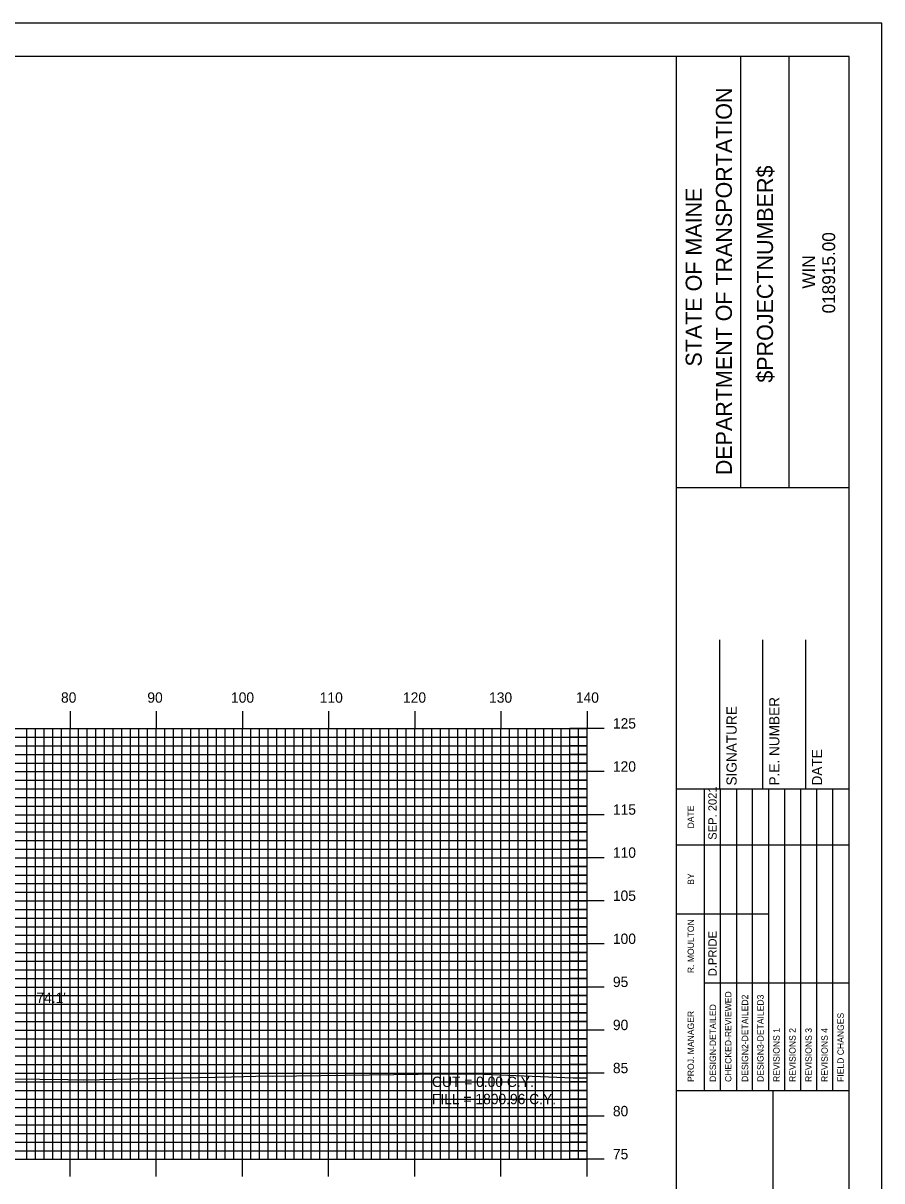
# Model space of a CAD drawing. Extents: x -302 to 42, y -1658 to -1438.
# Drawn here: x -61.3 to 38.3, y -1572.1 to -1437.7 of the extents above; entities that cross this region are included whole.
import ezdxf

# ---------------------------------------------------------------- set-up
doc = ezdxf.new("R2010")
doc.units = 0
for name, color, linetype in [('BORDER', 7, 'Continuous'), ('D_Text_Standard', 7, 'Continuous'), ('H_V ANNOTATION', 7, 'Continuous'), ('MAJOR', 7, 'Continuous'), ('MINOR', 7, 'Continuous'), ('PLOT BOUNDARY', 7, 'Continuous'), ('S_Roadway_Centerline', 7, 'Continuous')]:
    doc.layers.add(name, color=color, linetype=linetype)

msp = doc.modelspace()

# ---------------------------------------------------------------- linework, layer by layer
at = {"layer": 'BORDER'}
for p, q in [((14.51, -1651.6), (14.51, -1441.6)), ((21.97, -1491.61), (21.97, -1441.61)), ((27.56, -1491.61), (27.56, -1441.61)), ((14.51, -1491.62), (34.51, -1491.62)), ((19.51, -1526.6), (19.51, -1509.3)), ((24.51, -1526.6), (24.51, -1509.3)), ((29.51, -1526.6), (29.51, -1509.3)), ((14.51, -1526.6), (34.51, -1526.6)), ((14.51, -1561.6), (34.51, -1561.6)), ((25.69, -1631.6), (25.69, -1561.6))]:
    msp.add_line(p, q, dxfattribs=at)
msp.add_lwpolyline([(-285.49, -1651.6), (34.51, -1651.6), (34.51, -1441.6), (-285.49, -1441.6)], close=True, dxfattribs=at)
for points in [[(17.74, -1533.1), (17.74, -1526.6)], [(19.6, -1561.59), (19.6, -1526.6)], [(21.47, -1526.6), (21.47, -1561.59)], [(23.33, -1561.59), (23.33, -1526.6)], [(25.19, -1561.59), (25.19, -1526.6)], [(27.06, -1561.59), (27.06, -1526.6)], [(28.92, -1561.59), (28.92, -1526.6)], [(30.78, -1561.59), (30.78, -1526.6)], [(32.65, -1561.59), (32.65, -1526.6)], [(17.74, -1561.59), (17.74, -1528.01)], [(14.51, -1533.1), (34.51, -1533.1)], [(14.51, -1541.1), (17.74, -1541.1)], [(17.74, -1541.1), (25.19, -1541.1)], [(17.74, -1549.1), (34.51, -1549.1)]]:
    msp.add_lwpolyline(points, dxfattribs=at)
at = {"layer": 'MAJOR'}
for p, q in [((-55.89, -1517.6), (-55.89, -1519.6)), ((-45.89, -1517.6), (-45.89, -1519.6)), ((-35.89, -1517.6), (-35.89, -1519.6)), ((-25.89, -1517.6), (-25.89, -1519.6)), ((-15.89, -1517.6), (-15.89, -1519.6)), ((-5.89, -1517.6), (-5.89, -1519.6)), ((4.11, -1517.6), (4.11, -1519.6)), ((-275.89, -1519.6), (4.11, -1519.6)), ((-275.89, -1519.6), (4.11, -1519.6)), ((-55.89, -1569.6), (-55.89, -1519.6)), ((-45.89, -1569.6), (-45.89, -1519.6)), ((-35.89, -1569.6), (-35.89, -1519.6)), ((-25.89, -1569.6), (-25.89, -1519.6)), ((-15.89, -1569.6), (-15.89, -1519.6)), ((-5.89, -1569.6), (-5.89, -1519.6)), ((6.11, -1519.6), (2.1, -1519.6)), ((4.11, -1569.6), (4.11, -1519.6)), ((4.11, -1569.6), (4.11, -1519.6)), ((-275.89, -1524.6), (4.11, -1524.6)), ((6.11, -1524.6), (2.1, -1524.6)), ((-275.89, -1529.6), (4.11, -1529.6)), ((6.11, -1529.6), (2.1, -1529.6)), ((-275.89, -1534.6), (4.11, -1534.6)), ((6.11, -1534.6), (2.1, -1534.6)), ((-275.89, -1539.6), (4.11, -1539.6)), ((6.11, -1539.6), (2.1, -1539.6)), ((-275.89, -1544.6), (4.11, -1544.6)), ((6.11, -1544.6), (2.1, -1544.6)), ((-275.89, -1549.6), (4.11, -1549.6)), ((6.11, -1549.6), (2.1, -1549.6)), ((-275.89, -1554.6), (4.11, -1554.6)), ((6.11, -1554.6), (2.1, -1554.6)), ((-275.89, -1559.6), (4.11, -1559.6)), ((6.11, -1559.6), (2.1, -1559.6)), ((-275.89, -1564.6), (4.11, -1564.6)), ((6.11, -1564.6), (2.1, -1564.6)), ((-275.89, -1569.6), (4.11, -1569.6)), ((-275.89, -1569.6), (4.11, -1569.6)), ((-55.89, -1571.61), (-55.89, -1569.6)), ((-45.89, -1571.61), (-45.89, -1569.6)), ((-35.89, -1571.61), (-35.89, -1569.6)), ((-25.89, -1571.61), (-25.89, -1569.6)), ((-15.89, -1571.61), (-15.89, -1569.6)), ((-5.89, -1571.61), (-5.89, -1569.6)), ((6.11, -1569.6), (2.1, -1569.6)), ((4.11, -1571.61), (4.11, -1569.6))]:
    msp.add_line(p, q, dxfattribs=at)
at = {"layer": 'MINOR'}
for p, q in [((-60.89, -1569.6), (-60.89, -1519.6)), ((-59.89, -1569.6), (-59.89, -1519.6)), ((-58.89, -1569.6), (-58.89, -1519.6)), ((-57.89, -1569.6), (-57.89, -1519.6)), ((-56.89, -1569.6), (-56.89, -1519.6)), ((-54.89, -1569.6), (-54.89, -1519.6)), ((-53.89, -1569.6), (-53.89, -1519.6)), ((-52.89, -1569.6), (-52.89, -1519.6)), ((-51.89, -1569.6), (-51.89, -1519.6)), ((-50.89, -1569.6), (-50.89, -1519.6)), ((-49.89, -1569.6), (-49.89, -1519.6)), ((-48.89, -1569.6), (-48.89, -1519.6)), ((-47.89, -1569.6), (-47.89, -1519.6)), ((-46.89, -1569.6), (-46.89, -1519.6)), ((-44.89, -1569.6), (-44.89, -1519.6)), ((-43.89, -1569.6), (-43.89, -1519.6)), ((-42.89, -1569.6), (-42.89, -1519.6)), ((-41.89, -1569.6), (-41.89, -1519.6)), ((-40.89, -1569.6), (-40.89, -1519.6)), ((-39.89, -1569.6), (-39.89, -1519.6)), ((-38.89, -1569.6), (-38.89, -1519.6)), ((-37.89, -1569.6), (-37.89, -1519.6)), ((-36.89, -1569.6), (-36.89, -1519.6)), ((-34.89, -1569.6), (-34.89, -1519.6)), ((-33.89, -1569.6), (-33.89, -1519.6)), ((-32.89, -1569.6), (-32.89, -1519.6)), ((-31.89, -1569.6), (-31.89, -1519.6)), ((-30.89, -1569.6), (-30.89, -1519.6)), ((-29.89, -1569.6), (-29.89, -1519.6)), ((-28.89, -1569.6), (-28.89, -1519.6)), ((-27.89, -1569.6), (-27.89, -1519.6)), ((-26.89, -1569.6), (-26.89, -1519.6)), ((-24.89, -1569.6), (-24.89, -1519.6)), ((-23.89, -1569.6), (-23.89, -1519.6)), ((-22.89, -1569.6), (-22.89, -1519.6)), ((-21.89, -1569.6), (-21.89, -1519.6)), ((-20.89, -1569.6), (-20.89, -1519.6)), ((-19.89, -1569.6), (-19.89, -1519.6)), ((-18.89, -1569.6), (-18.89, -1519.6)), ((-17.89, -1569.6), (-17.89, -1519.6)), ((-16.89, -1569.6), (-16.89, -1519.6)), ((-14.89, -1569.6), (-14.89, -1519.6)), ((-13.89, -1569.6), (-13.89, -1519.6)), ((-12.89, -1569.6), (-12.89, -1519.6)), ((-11.89, -1569.6), (-11.89, -1519.6)), ((-10.89, -1569.6), (-10.89, -1519.6)), ((-9.89, -1569.6), (-9.89, -1519.6)), ((-8.89, -1569.6), (-8.89, -1519.6)), ((-7.89, -1569.6), (-7.89, -1519.6)), ((-6.89, -1569.6), (-6.89, -1519.6)), ((-4.89, -1569.6), (-4.89, -1519.6)), ((-3.89, -1569.6), (-3.89, -1519.6)), ((-2.89, -1569.6), (-2.89, -1519.6)), ((-1.89, -1569.6), (-1.89, -1519.6)), ((-0.89, -1569.6), (-0.89, -1519.6)), ((0.11, -1569.6), (0.11, -1519.6)), ((1.11, -1569.6), (1.11, -1519.6)), ((2.11, -1569.6), (2.11, -1519.6)), ((3.11, -1569.6), (3.11, -1519.6)), ((-275.89, -1520.6), (4.11, -1520.6)), ((4.11, -1520.6), (2.1, -1520.6)), ((-275.89, -1521.6), (4.11, -1521.6)), ((4.11, -1521.6), (2.1, -1521.6)), ((-275.89, -1522.6), (4.11, -1522.6)), ((-275.89, -1523.6), (4.11, -1523.6)), ((4.11, -1522.6), (2.1, -1522.6)), ((4.11, -1523.6), (2.1, -1523.6)), ((-275.89, -1525.6), (4.11, -1525.6)), ((4.11, -1525.6), (2.1, -1525.6)), ((-275.89, -1526.6), (4.11, -1526.6)), ((-275.89, -1527.6), (4.11, -1527.6)), ((4.11, -1526.6), (2.1, -1526.6)), ((4.11, -1527.6), (2.1, -1527.6)), ((-275.89, -1528.6), (4.11, -1528.6)), ((4.11, -1528.6), (2.1, -1528.6)), ((-275.89, -1530.6), (4.11, -1530.6)), ((-275.89, -1531.6), (4.11, -1531.6)), ((4.11, -1530.6), (2.1, -1530.6)), ((4.11, -1531.6), (2.1, -1531.6)), ((-275.89, -1532.6), (4.11, -1532.6)), ((4.11, -1532.6), (2.1, -1532.6)), ((-275.89, -1533.6), (4.11, -1533.6)), ((4.11, -1533.6), (2.1, -1533.6)), ((-275.89, -1535.6), (4.11, -1535.6)), ((4.11, -1535.6), (2.1, -1535.6)), ((-275.89, -1536.6), (4.11, -1536.6)), ((4.11, -1536.6), (2.1, -1536.6)), ((-275.89, -1537.6), (4.11, -1537.6)), ((4.11, -1537.6), (2.1, -1537.6)), ((-275.89, -1538.6), (4.11, -1538.6)), ((4.11, -1538.6), (2.1, -1538.6)), ((-275.89, -1540.6), (4.11, -1540.6)), ((4.11, -1540.6), (2.1, -1540.6)), ((-275.89, -1541.6), (4.11, -1541.6)), ((-275.89, -1542.6), (4.11, -1542.6)), ((4.11, -1541.6), (2.1, -1541.6)), ((4.11, -1542.6), (2.1, -1542.6)), ((-275.89, -1543.6), (4.11, -1543.6)), ((4.11, -1543.6), (2.1, -1543.6)), ((-275.89, -1545.6), (4.11, -1545.6)), ((-275.89, -1546.6), (4.11, -1546.6)), ((4.11, -1545.6), (2.1, -1545.6)), ((4.11, -1546.6), (2.1, -1546.6)), ((-275.89, -1547.6), (4.11, -1547.6)), ((4.11, -1547.6), (2.1, -1547.6)), ((-275.89, -1548.6), (4.11, -1548.6)), ((4.11, -1548.6), (2.1, -1548.6)), ((-275.89, -1550.6), (4.11, -1550.6)), ((4.11, -1550.6), (2.1, -1550.6)), ((-275.89, -1551.6), (4.11, -1551.6)), ((4.11, -1551.6), (2.1, -1551.6)), ((-275.89, -1552.6), (4.11, -1552.6)), ((4.11, -1552.6), (2.1, -1552.6)), ((-275.89, -1553.6), (4.11, -1553.6)), ((4.11, -1553.6), (2.1, -1553.6)), ((-275.89, -1555.6), (4.11, -1555.6)), ((4.11, -1555.6), (2.1, -1555.6)), ((-275.89, -1556.6), (4.11, -1556.6)), ((4.11, -1556.6), (2.1, -1556.6)), ((-275.89, -1557.6), (4.11, -1557.6)), ((-275.89, -1558.6), (4.11, -1558.6)), ((4.11, -1557.6), (2.1, -1557.6)), ((4.11, -1558.6), (2.1, -1558.6)), ((-275.89, -1560.6), (4.11, -1560.6)), ((4.11, -1560.6), (2.1, -1560.6)), ((-275.89, -1561.6), (4.11, -1561.6)), ((-275.89, -1562.6), (4.11, -1562.6)), ((4.11, -1561.6), (2.1, -1561.6)), ((4.11, -1562.6), (2.1, -1562.6)), ((-275.89, -1563.6), (4.11, -1563.6)), ((4.11, -1563.6), (2.1, -1563.6)), ((-275.89, -1565.6), (4.11, -1565.6)), ((-275.89, -1566.6), (4.11, -1566.6)), ((4.11, -1565.6), (2.1, -1565.6)), ((4.11, -1566.6), (2.1, -1566.6)), ((-275.89, -1567.6), (4.11, -1567.6)), ((4.11, -1567.6), (2.1, -1567.6)), ((-275.89, -1568.6), (4.11, -1568.6)), ((4.11, -1568.6), (2.1, -1568.6))]:
    msp.add_line(p, q, dxfattribs=at)
at = {"layer": 'PLOT BOUNDARY'}
msp.add_lwpolyline([(-301.68, -1657.72), (38.32, -1657.72), (38.32, -1437.72), (-301.68, -1437.72)], close=True, dxfattribs=at)
at = {"layer": 'S_Roadway_Centerline'}
msp.add_lwpolyline([(-182.37, -1560.12), (-163.66, -1560.2), (-158.39, -1560.13), (-149.33, -1559.9), (-132.18, -1560.13), (-129.56, -1560), (-119.95, -1559.84), (-114.22, -1559.62), (-107.19, -1559.75), (-97.62, -1559.88), (-91.11, -1559.95), (-82.07, -1560.13), (-75.71, -1560.09), (-56.16, -1560.33), (-54.35, -1560.37), (-37.14, -1560.02), (-32.89, -1559.92), (-32.43, -1559.93), (-12.66, -1559.66), (-7.94, -1559.7), (2.5, -1560.13), (4.11, -1560.13)], dxfattribs=at)

# ---------------------------------------------------------------- texts
at = {"layer": 'BORDER'}
for s, height, p in [('DEPARTMENT OF TRANSPORTATION', 1.8635, (20.92, -1490.19)), ('$PROJECTNUMBER$', 1.8635, (25.69, -1479.45)), ('STATE OF MAINE', 1.8635, (17.42, -1477.58)), ('018915.00', 1.491, (32.9, -1471.41)), ('WIN', 1.491, (30.58, -1468.54)), ('SIGNATURE', 1.181, (21.47, -1526.21)), ('P.E. NUMBER', 1.1811, (26.43, -1526.21)), ('DATE', 1.181, (31.39, -1526.21)), ('SEP. 2021', 0.969, (19.15, -1532.51)), ('DATE', 0.743, (16.52, -1531.19)), ('BY', 0.743, (16.52, -1537.73)), ('R. MOULTON', 0.745, (16.52, -1547.99)), ('D.PRIDE', 0.969, (19.15, -1548.35)), ('CHECKED-REVIEWED', 0.7455, (20.87, -1560.62)), ('DESIGN2-DETAILED2', 0.7455, (22.81, -1560.62)), ('DESIGN3-DETAILED3', 0.7455, (24.6, -1560.62)), ('DESIGN-DETAILED', 0.7455, (19.08, -1560.62)), ('PROJ. MANAGER', 0.7455, (16.52, -1560.62)), ('FIELD CHANGES', 0.7455, (33.91, -1560.62)), ('REVISIONS 1', 0.7455, (26.46, -1560.62)), ('REVISIONS 2', 0.7455, (28.32, -1560.62)), ('REVISIONS 3', 0.7455, (30.19, -1560.62)), ('REVISIONS 4', 0.7455, (32.05, -1560.62))]:
    msp.add_text(s, height=height, rotation=90, dxfattribs=at).set_placement(p)
at = {"layer": 'D_Text_Standard'}
for s, p in [("74.1'", (-59.8, -1551.45)), ('CUT = 0.00 C.Y.', (-13.89, -1561.2)), ('FILL = 1800.96 C.Y.', (-13.89, -1563.2))]:
    msp.add_text(s, height=1.2, dxfattribs=at).set_placement(p)
at = {"layer": 'H_V ANNOTATION'}
for s, p in [('80', (-56.94, -1516.6)), ('90', (-46.92, -1516.6)), ('100', (-37.21, -1516.6)), ('110', (-26.91, -1516.6)), ('120', (-17.25, -1516.6)), ('130', (-7.26, -1516.6)), ('140', (2.81, -1516.6)), ('125', (7.11, -1519.6)), ('120', (7.11, -1524.6)), ('115', (7.11, -1529.6)), ('110', (7.11, -1534.6)), ('105', (7.11, -1539.6)), ('100', (7.11, -1544.6)), ('95', (7.11, -1549.6)), ('90', (7.11, -1554.6)), ('85', (7.11, -1559.6)), ('80', (7.11, -1564.6)), ('75', (7.11, -1569.6))]:
    msp.add_text(s, height=1.2, dxfattribs=at).set_placement(p)

doc.saveas('drawing.dxf')
